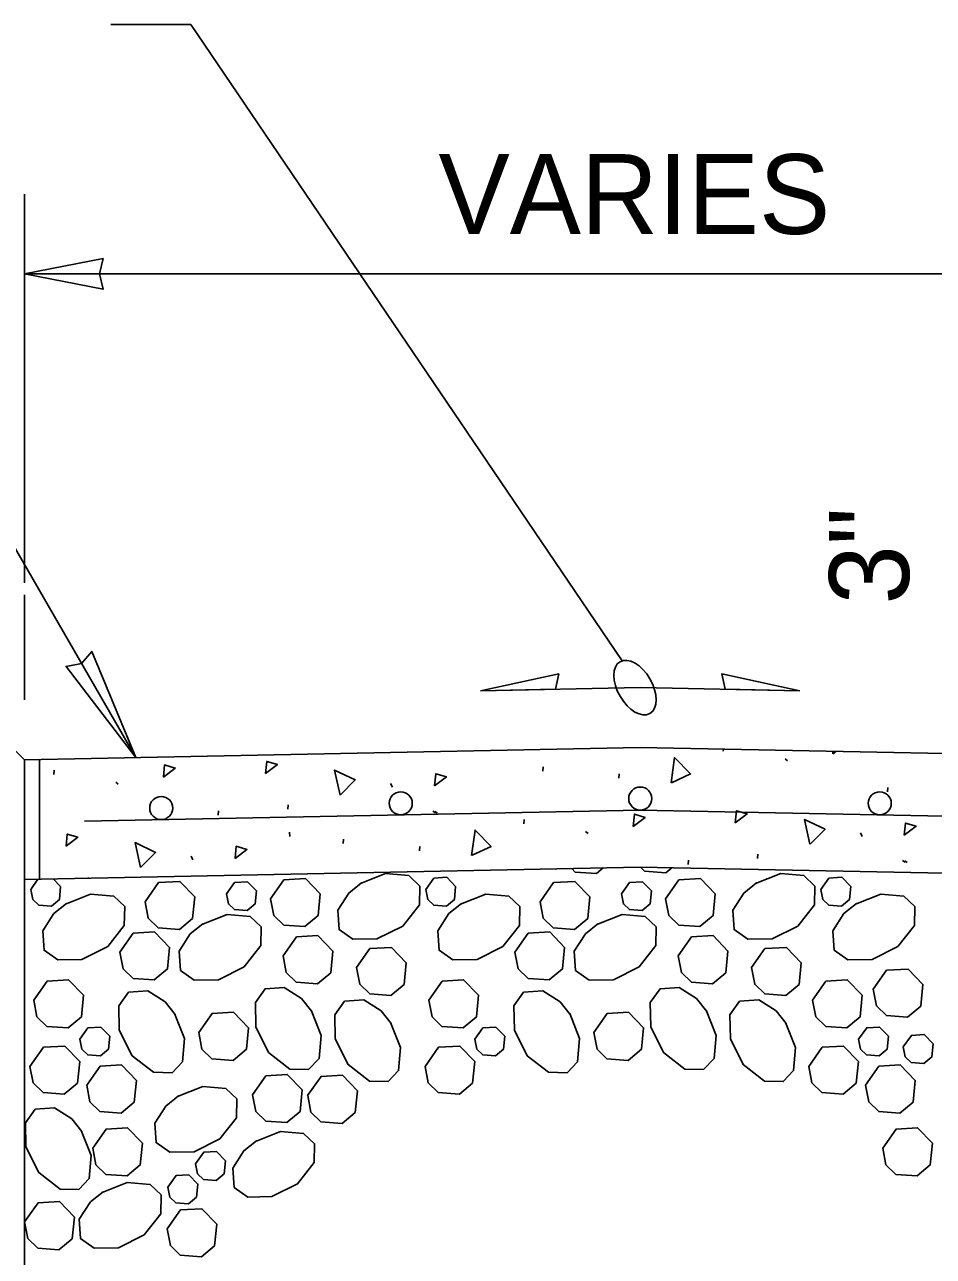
# Model space of a CAD drawing. Extents: x 99862 to 103151, y 100000 to 102076.
# Drawn here: x 100195.7 to 100377.8, y 100719.1 to 100966 of the extents above; entities that cross this region are included whole.
import ezdxf

# ---------------------------------------------------------------- set-up
doc = ezdxf.new("R2010")
doc.units = 0
for name, color, linetype in [('Level 10', 7, 'Continuous'), ('Level 13', 7, 'Continuous'), ('Level 15', 7, 'Continuous'), ('Level 19', 7, 'Continuous'), ('Level 2', 7, 'Continuous'), ('Level 20', 7, 'Continuous'), ('Level 45', 7, 'Continuous'), ('Level 56', 7, 'Continuous')]:
    doc.layers.add(name, color=color, linetype=linetype)

msp = doc.modelspace()

# ---------------------------------------------------------------- linework, layer by layer
at = {"layer": 'Level 10'}
for p in [(100207.7, 100806.33), (100430.38, 100806.33)]:
    msp.add_line(p, (100319.04, 100808.56), dxfattribs=at)
for centre in [(100319.04, 100810.87), (100223.06, 100808.95), (100271.05, 100809.91), (100367.03, 100809.91)]:
    msp.add_circle(centre, 2.31, dxfattribs=at)
at = {"layer": 'Level 13'}
for p, q in [((100335.67, 100820.36), (100335.7, 100820.77)), ((100348.05, 100818.81), (100348.57, 100818.44)), ((100201.57, 100815.69), (100201.63, 100816.56)), ((100299.51, 100816.37), (100299.57, 100817.25)), ((100314.78, 100814.93), (100314.84, 100815.8)), ((100213.95, 100814.15), (100214.46, 100813.77)), ((100269.03, 100813.87), (100269.38, 100813.15)), ((100368.6, 100812.21), (100368.66, 100813.09)), ((100234.49, 100807.55), (100234.55, 100808.42)), ((100248.42, 100808.74), (100248.48, 100809.61)), ((100277.48, 100808.36), (100278, 100807.98)), ((100277.88, 100808.29), (100278.4, 100807.91)), ((100295.7, 100805.81), (100295.76, 100806.68)), ((100248.85, 100803.23), (100248.79, 100804.1)), ((100259.54, 100801.83), (100259.6, 100802.7)), ((100308.08, 100804.27), (100308.59, 100803.89)), ((100363.16, 100803.98), (100363.51, 100803.26)), ((100274.81, 100800.38), (100274.87, 100801.25)), ((100229.05, 100799.32), (100229.41, 100798.6)), ((100328.63, 100797.66), (100328.69, 100798.54)), ((100342.55, 100798.86), (100342.62, 100799.73)), ((100371.61, 100798.47), (100372.13, 100798.09)), ((100372.02, 100798.41), (100372.53, 100798.03)), ((100208.5, 100794.89), (100208.51, 100795.07))]:
    msp.add_line(p, q, dxfattribs=at)
for points in [[(100357.6, 100819.83), (100357.65, 100820.33)], [(100358.24, 100820.32), (100357.6, 100819.83)], [(100223.5, 100815.17), (100223.74, 100817.62), (100225.86, 100816.97), (100223.5, 100815.17)], [(100243.96, 100815.86), (100244.2, 100818.31), (100246.33, 100817.67), (100243.96, 100815.86)], [(100325.23, 100814.01), (100325.93, 100819.08), (100329.11, 100815.8), (100325.31, 100814.04)], [(100258.89, 100811.57), (100257.81, 100816.58), (100261.93, 100814.59), (100258.96, 100811.63)], [(100277.82, 100813.39), (100278.06, 100815.85), (100280.19, 100815.2), (100277.82, 100813.39)], [(100317.63, 100805.29), (100317.87, 100807.74), (100320, 100807.09), (100317.63, 100805.29)], [(100338.09, 100805.98), (100338.33, 100808.43), (100340.46, 100807.78), (100338.09, 100805.98)], [(100353.02, 100801.69), (100351.95, 100806.7), (100356.06, 100804.7), (100353.09, 100801.75)], [(100371.95, 100803.51), (100372.2, 100805.96), (100374.32, 100805.32), (100371.95, 100803.51)], [(100203.99, 100801.31), (100204.23, 100803.76), (100206.35, 100803.12), (100203.99, 100801.31)], [(100285.26, 100799.46), (100285.96, 100804.53), (100289.14, 100801.25), (100285.34, 100799.49)], [(100218.92, 100797.02), (100217.84, 100802.04), (100221.95, 100800.04), (100218.98, 100797.08)], [(100237.85, 100798.85), (100238.09, 100801.3), (100240.22, 100800.65), (100237.85, 100798.85)]]:
    msp.add_lwpolyline(points, dxfattribs=at)
at = {"layer": 'Level 15'}
for p, q in [((100212.98, 100965.99), (100228.98, 100965.99)), ((100315.4, 100838.48), (100228.98, 100965.99)), ((100195.7, 100854.08), (100195.7, 100932.03)), ((100195.7, 100916.03), (100270.08, 100916.03)), ((100270.08, 100916.03), (100442.38, 100916.03)), ((100217.99, 100819.08), (100177.58, 100889.08)), ((100195.7, 100830.64), (100195.7, 100851.7)), ((100287.05, 100832.46), (100319.04, 100833.1)), ((100351.03, 100832.46), (100319.04, 100833.1))]:
    msp.add_line(p, q, dxfattribs=at)
for points in [[(100195.7, 100916.03), (100211.42, 100912.95), (100210.7, 100916.03), (100211.42, 100919.11)], [(100217.99, 100819.08), (100209.16, 100840.35), (100207.11, 100837.94), (100203.99, 100837.36)], [(100287.05, 100832.47), (100302.04, 100832.77), (100302.71, 100835.86)], [(100351.03, 100832.47), (100335.37, 100835.86), (100336.04, 100832.77)]]:
    msp.add_lwpolyline(points, close=True, dxfattribs=at)
msp.add_ellipse((100317.99, 100833.1), major_axis=(-3, 5.2), ratio=0.57735, dxfattribs=at)
at = {"layer": 'Level 19'}
for p, q in [((100198.7, 100818.7), (100195.7, 100818.64)), ((100195.7, 100818.64), (100195.7, 100794.64)), ((100198.7, 100794.7), (100198.7, 100818.7)), ((100195.7, 100794.64), (100198.7, 100794.7))]:
    msp.add_line(p, q, dxfattribs=at)
at = {"layer": 'Level 2'}
for p in [(100189.7, 100824.64), (100195.7, 100488.64)]:
    msp.add_line(p, (100195.7, 100818.64), dxfattribs=at)
at = {"layer": 'Level 45'}
for points in [[(100263, 100793.83), (100268.03, 100795.82), (100272.65, 100795.42), (100274.85, 100793.33), (100274.78, 100789.58), (100271.44, 100785.32), (100266.29, 100782.75), (100261.44, 100782.66), (100258.7, 100784.6), (100258.45, 100788.47), (100260.66, 100791.93), (100263.2, 100793.95)], [(100311.63, 100796.96), (100310.27, 100795.82), (100306.03, 100796.13), (100305.3, 100796.83)], [(100325.34, 100796.98), (100324.14, 100795.98), (100319.9, 100796.29), (100319.06, 100797.1)], [(100342.15, 100793.83), (100347.18, 100795.82), (100351.8, 100795.42), (100354, 100793.33), (100353.93, 100789.58), (100350.59, 100785.32), (100345.44, 100782.75), (100340.59, 100782.66), (100337.85, 100784.6), (100337.59, 100788.47), (100339.81, 100791.93), (100342.35, 100793.95)], [(100195.7, 100793.33), (100195.7, 100793.33), (100195.7, 100793.31)], [(100201.44, 100794.75), (100202.91, 100793.23), (100202.65, 100790.63), (100201.06, 100789.3), (100198.51, 100789.49), (100197.32, 100790.65), (100196.93, 100792.64)], [(100196.93, 100792.64), (100198.37, 100794.69)], [(100219.83, 100790.19), (100222.51, 100794.01), (100226.81, 100794.26), (100229.79, 100791.16), (100229.36, 100786.83), (100226.71, 100784.62), (100222.47, 100784.93), (100220.48, 100786.86), (100219.83, 100790.19)], [(100236.14, 100791.76), (100237.76, 100794.05), (100240.33, 100794.2), (100242.12, 100792.34), (100241.86, 100789.74), (100240.27, 100788.42), (100237.73, 100788.6), (100236.53, 100789.76), (100236.14, 100791.76)], [(100244.95, 100790.77), (100247.64, 100794.59), (100251.94, 100794.84), (100254.92, 100791.74), (100254.49, 100787.41), (100251.84, 100785.2), (100247.6, 100785.51), (100245.6, 100787.44), (100244.96, 100790.77)], [(100276.07, 100792.64), (100277.69, 100794.94), (100280.26, 100795.08), (100282.05, 100793.23), (100281.8, 100790.63), (100280.2, 100789.3), (100277.66, 100789.49), (100276.46, 100790.65), (100276.08, 100792.64)], [(100298.97, 100790.19), (100301.66, 100794.01), (100305.96, 100794.26), (100308.94, 100791.16), (100308.51, 100786.83), (100305.86, 100784.62), (100301.62, 100784.93), (100299.62, 100786.86), (100298.98, 100790.19)], [(100315.29, 100791.76), (100316.9, 100794.05), (100319.48, 100794.2), (100321.27, 100792.34), (100321.01, 100789.74), (100319.42, 100788.42), (100316.88, 100788.6), (100315.68, 100789.76), (100315.29, 100791.76)], [(100324.1, 100790.77), (100326.79, 100794.59), (100331.09, 100794.84), (100334.07, 100791.74), (100333.64, 100787.41), (100330.99, 100785.2), (100326.75, 100785.51), (100324.75, 100787.44), (100324.11, 100790.77)], [(100355.22, 100792.64), (100356.84, 100794.94), (100359.41, 100795.08), (100361.2, 100793.23), (100360.94, 100790.63), (100359.35, 100789.3), (100356.81, 100789.49), (100355.61, 100790.65), (100355.22, 100792.64)], [(100203.89, 100789.7), (100208.92, 100791.69), (100213.55, 100791.29), (100215.74, 100789.2), (100215.67, 100785.45), (100212.34, 100781.19), (100207.19, 100778.62), (100202.33, 100778.53), (100199.6, 100780.47), (100199.34, 100784.34), (100201.56, 100787.8), (100204.1, 100789.82)], [(100283.04, 100789.7), (100288.07, 100791.69), (100292.69, 100791.29), (100294.89, 100789.2), (100294.82, 100785.45), (100291.49, 100781.19), (100286.34, 100778.62), (100281.48, 100778.53), (100278.75, 100780.47), (100278.49, 100784.34), (100280.71, 100787.8), (100283.25, 100789.82)], [(100362.19, 100789.7), (100367.22, 100791.69), (100371.84, 100791.29), (100374.04, 100789.2), (100373.97, 100785.45), (100370.63, 100781.19), (100365.48, 100778.62), (100360.63, 100778.53), (100357.9, 100780.47), (100357.64, 100784.34), (100359.85, 100787.8), (100362.39, 100789.82)], [(100231.22, 100785.63), (100236.25, 100787.62), (100240.87, 100787.22), (100243.07, 100785.14), (100243, 100781.39), (100239.67, 100777.12), (100234.52, 100774.55), (100229.66, 100774.46), (100226.93, 100776.41), (100226.67, 100780.27), (100228.89, 100783.73), (100231.43, 100785.76)], [(100310.37, 100785.63), (100315.4, 100787.62), (100320.02, 100787.22), (100322.22, 100785.14), (100322.15, 100781.39), (100318.82, 100777.12), (100313.66, 100774.55), (100308.81, 100774.46), (100306.08, 100776.41), (100305.82, 100780.27), (100308.04, 100783.73), (100310.57, 100785.76)], [(100214.77, 100780.07), (100217.45, 100783.89), (100221.75, 100784.14), (100224.73, 100781.04), (100224.3, 100776.71), (100221.65, 100774.5), (100217.41, 100774.81), (100215.41, 100776.74), (100214.77, 100780.07)], [(100247.48, 100779.32), (100250.17, 100783.14), (100254.47, 100783.39), (100257.45, 100780.29), (100257.02, 100775.95), (100254.37, 100773.75), (100250.13, 100774.06), (100248.13, 100775.99), (100247.49, 100779.31)], [(100293.91, 100780.07), (100296.6, 100783.89), (100300.9, 100784.14), (100303.88, 100781.04), (100303.45, 100776.71), (100300.8, 100774.5), (100296.56, 100774.81), (100294.56, 100776.74), (100293.92, 100780.07)], [(100326.63, 100779.32), (100329.32, 100783.14), (100333.62, 100783.39), (100336.6, 100780.29), (100336.17, 100775.95), (100333.52, 100773.75), (100329.28, 100774.06), (100327.28, 100775.99), (100326.64, 100779.31)], [(100262.19, 100776.97), (100264.88, 100780.8), (100269.17, 100781.04), (100272.15, 100777.95), (100271.72, 100773.61), (100269.07, 100771.41), (100264.83, 100771.71), (100262.84, 100773.65), (100262.19, 100776.97)], [(100341.34, 100776.97), (100344.02, 100780.8), (100348.32, 100781.04), (100351.3, 100777.95), (100350.87, 100773.61), (100348.22, 100771.41), (100343.98, 100771.71), (100341.98, 100773.65), (100341.34, 100776.97)], [(100365.7, 100772.63), (100368.39, 100776.46), (100372.69, 100776.7), (100375.67, 100773.61), (100375.24, 100769.27), (100372.59, 100767.06), (100368.35, 100767.37), (100366.35, 100769.3), (100365.71, 100772.63)], [(100197.52, 100770.47), (100200.21, 100774.29), (100204.5, 100774.54), (100207.49, 100771.44), (100207.06, 100767.11), (100204.4, 100764.9), (100200.16, 100765.21), (100198.17, 100767.14), (100197.52, 100770.47)], [(100276.67, 100770.47), (100279.36, 100774.29), (100283.65, 100774.54), (100286.64, 100771.44), (100286.21, 100767.11), (100283.55, 100764.9), (100279.31, 100765.21), (100277.32, 100767.14), (100276.67, 100770.47)], [(100353.55, 100770.47), (100356.24, 100774.29), (100360.53, 100774.54), (100363.52, 100771.44), (100363.09, 100767.11), (100360.43, 100764.9), (100356.2, 100765.21), (100354.2, 100767.14), (100353.55, 100770.47)], [(100225.75, 100767.77), (100227.74, 100762.74), (100227.35, 100758.12), (100225.26, 100755.92), (100221.51, 100755.99), (100217.25, 100759.32), (100214.67, 100764.47), (100214.59, 100769.33), (100216.53, 100772.06), (100220.39, 100772.32), (100223.85, 100770.1), (100225.88, 100767.56)], [(100253.08, 100768.42), (100255.08, 100763.39), (100254.68, 100758.77), (100252.59, 100756.57), (100248.84, 100756.64), (100244.58, 100759.97), (100242, 100765.12), (100241.92, 100769.98), (100243.86, 100772.71), (100247.72, 100772.97), (100251.18, 100770.76), (100253.21, 100768.21)], [(100304.9, 100767.77), (100306.89, 100762.74), (100306.49, 100758.12), (100304.41, 100755.92), (100300.66, 100755.99), (100296.39, 100759.32), (100293.82, 100764.47), (100293.73, 100769.33), (100295.68, 100772.06), (100299.54, 100772.32), (100303, 100770.1), (100305.03, 100767.56)], [(100332.23, 100768.42), (100334.22, 100763.39), (100333.82, 100758.77), (100331.74, 100756.57), (100327.99, 100756.64), (100323.73, 100759.97), (100321.15, 100765.12), (100321.06, 100769.98), (100323.01, 100772.71), (100326.87, 100772.97), (100330.33, 100770.76), (100332.36, 100768.21)], [(100269.02, 100765.98), (100271.02, 100760.95), (100270.62, 100756.33), (100268.53, 100754.13), (100264.78, 100754.2), (100260.52, 100757.53), (100257.94, 100762.68), (100257.86, 100767.54), (100259.8, 100770.27), (100263.67, 100770.53), (100267.13, 100768.31), (100269.15, 100765.77)], [(100348.17, 100765.98), (100350.17, 100760.95), (100349.77, 100756.33), (100347.68, 100754.13), (100343.93, 100754.2), (100339.67, 100757.53), (100337.09, 100762.68), (100337.01, 100767.54), (100338.95, 100770.27), (100342.82, 100770.53), (100346.28, 100768.31), (100348.3, 100765.77)], [(100230.58, 100763.96), (100233.27, 100767.79), (100237.56, 100768.03), (100240.55, 100764.94), (100240.12, 100760.6), (100237.46, 100758.39), (100233.22, 100758.7), (100231.23, 100760.64), (100230.58, 100763.96)], [(100309.73, 100763.96), (100312.42, 100767.79), (100316.71, 100768.03), (100319.7, 100764.94), (100319.26, 100760.6), (100316.61, 100758.39), (100312.37, 100758.7), (100310.38, 100760.64), (100309.73, 100763.96)], [(100206.76, 100762.63), (100208.37, 100764.93), (100210.95, 100765.07), (100212.74, 100763.22), (100212.48, 100760.61), (100210.89, 100759.29), (100208.35, 100759.47), (100207.15, 100760.64), (100206.76, 100762.63)], [(100285.91, 100762.63), (100287.52, 100764.93), (100290.1, 100765.07), (100291.89, 100763.22), (100291.63, 100760.61), (100290.04, 100759.29), (100287.5, 100759.47), (100286.3, 100760.64), (100285.91, 100762.63)], [(100362.79, 100762.63), (100364.41, 100764.93), (100366.98, 100765.07), (100368.77, 100763.22), (100368.51, 100760.61), (100366.92, 100759.29), (100364.38, 100759.47), (100363.18, 100760.64), (100362.79, 100762.63)], [(100371.75, 100761.11), (100373.37, 100763.4), (100375.94, 100763.55), (100377.73, 100761.69), (100377.47, 100759.09), (100375.88, 100757.77), (100373.34, 100757.95), (100372.14, 100759.11), (100371.75, 100761.1)], [(100196.77, 100757.18), (100199.46, 100761.01), (100203.75, 100761.26), (100206.74, 100758.16), (100206.3, 100753.82), (100203.65, 100751.62), (100199.41, 100751.93), (100197.42, 100753.86), (100196.77, 100757.18)], [(100275.92, 100757.18), (100278.61, 100761.01), (100282.9, 100761.26), (100285.88, 100758.16), (100285.45, 100753.82), (100282.8, 100751.62), (100278.56, 100751.93), (100276.57, 100753.86), (100275.92, 100757.18)], [(100352.8, 100757.18), (100355.49, 100761.01), (100359.78, 100761.26), (100362.77, 100758.16), (100362.33, 100753.82), (100359.68, 100751.62), (100355.44, 100751.93), (100353.45, 100753.86), (100352.8, 100757.18)], [(100208.13, 100753.39), (100210.82, 100757.21), (100215.11, 100757.46), (100218.1, 100754.36), (100217.67, 100750.03), (100215.01, 100747.82), (100210.77, 100748.13), (100208.78, 100750.06), (100208.13, 100753.39)], [(100364.16, 100753.39), (100366.85, 100757.21), (100371.14, 100757.46), (100374.13, 100754.36), (100373.7, 100750.03), (100371.04, 100747.82), (100366.81, 100748.13), (100364.81, 100750.06), (100364.16, 100753.39)], [(100241.34, 100751.49), (100244.03, 100755.32), (100248.33, 100755.56), (100251.31, 100752.47), (100250.88, 100748.13), (100248.23, 100745.92), (100243.99, 100746.23), (100241.99, 100748.17), (100241.35, 100751.49)], [(100252.4, 100751.33), (100255.09, 100755.15), (100259.39, 100755.4), (100262.37, 100752.3), (100261.94, 100747.97), (100259.29, 100745.76), (100255.05, 100746.07), (100253.05, 100748), (100252.41, 100751.33)], [(100226.34, 100751.14), (100231.37, 100753.14), (100235.99, 100752.74), (100238.19, 100750.65), (100238.12, 100746.9), (100234.79, 100742.64), (100229.64, 100740.06), (100224.78, 100739.98), (100222.05, 100741.92), (100221.79, 100745.79), (100224.01, 100749.24), (100226.55, 100751.27)], [(100207.04, 100744.34), (100209.04, 100739.31), (100208.64, 100734.69), (100206.55, 100732.49), (100202.8, 100732.56), (100198.54, 100735.9), (100195.96, 100741.05), (100195.88, 100745.9), (100197.82, 100748.64), (100201.69, 100748.9), (100205.15, 100746.68), (100207.17, 100744.14)], [(100209.33, 100740.8), (100212.02, 100744.63), (100216.31, 100744.87), (100219.29, 100741.78), (100218.86, 100737.44), (100216.21, 100735.23), (100211.97, 100735.54), (100209.98, 100737.48), (100209.33, 100740.8)], [(100241.95, 100742.15), (100246.98, 100744.15), (100251.6, 100743.75), (100253.8, 100741.66), (100253.73, 100737.91), (100250.4, 100733.65), (100245.24, 100731.07), (100240.39, 100730.99), (100237.66, 100732.93), (100237.4, 100736.8), (100239.61, 100740.26), (100242.15, 100742.28)], [(100367.62, 100740.8), (100370.31, 100744.63), (100374.61, 100744.87), (100377.59, 100741.78), (100377.16, 100737.44), (100374.51, 100735.23), (100370.27, 100735.54), (100368.27, 100737.48), (100367.63, 100740.8)], [(100229.96, 100737.66), (100231.58, 100739.96), (100234.15, 100740.11), (100235.94, 100738.25), (100235.69, 100735.65), (100234.09, 100734.32), (100231.55, 100734.51), (100230.35, 100735.67), (100229.96, 100737.66)], [(100211.21, 100731.91), (100216.24, 100733.9), (100220.86, 100733.5), (100223.06, 100731.41), (100222.99, 100727.66), (100219.65, 100723.4), (100214.5, 100720.83), (100209.65, 100720.74), (100206.91, 100722.68), (100206.65, 100726.55), (100208.87, 100730.01), (100211.41, 100732.04)], [(100224.41, 100733), (100226.03, 100735.29), (100228.6, 100735.44), (100230.4, 100733.58), (100230.14, 100730.98), (100228.55, 100729.66), (100226, 100729.84), (100224.8, 100731), (100224.42, 100733)], [(100195.7, 100726.01), (100198.39, 100729.83), (100202.68, 100730.08), (100205.67, 100726.99), (100205.24, 100722.65), (100202.58, 100720.44), (100198.34, 100720.75), (100196.35, 100722.68), (100195.7, 100726.01)], [(100224.24, 100724.59), (100226.93, 100728.42), (100231.22, 100728.66), (100234.2, 100725.57), (100233.77, 100721.23), (100231.12, 100719.02), (100226.88, 100719.33), (100224.89, 100721.27), (100224.24, 100724.59)]]:
    msp.add_lwpolyline(points, dxfattribs=at)
at = {"layer": 'Level 56'}
for p, q in [((100195.7, 100818.64), (100319.04, 100821.1)), ((100442.38, 100818.64), (100319.04, 100821.1)), ((100195.7, 100794.64), (100319.04, 100797.1)), ((100442.38, 100794.64), (100319.04, 100797.1))]:
    msp.add_line(p, q, dxfattribs=at)

# ---------------------------------------------------------------- texts
at = {"layer": 'Level 20'}
msp.add_text('VARIES', height=16, dxfattribs=at).set_placement((100278.62, 100924.03))
msp.add_text('3"', height=16, rotation=90, dxfattribs=at).set_placement((100372.89, 100849.76))

doc.saveas('drawing.dxf')
